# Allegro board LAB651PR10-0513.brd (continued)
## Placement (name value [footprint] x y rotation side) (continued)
RH72  10K_0402_5%  [R_0402]  160.79 13.39 180 top
RH73  100K_0402_5%  [R_0402]  144.81 21.19 180 top
RH74  0_0402_5%  [R_0402]  163.23 5.27 270 bottom
RH75  10K_0402_5%  [R_0402]  160.2 11.31 270 top
RH76  0_0402_5%  [R_0402]  161.77 5.27 270 bottom
RH77  0_0402_5%  [R0402_0OHM]  161.14 4.63 0 top
RH78  2.2K_0402_5%  [R_0402]  161.77 2.52 90 bottom
RH79  2.2K_0402_5%  [R_0402]  167.06 35.95 270 bottom
RH80  2.2K_0402_5%  [R_0402]  166.05 35.95 270 bottom
RH81  10K_0402_5%  [R_0402]  164.78 2.77 90 top
RH82  10K_0402_5%  [R_0402]  160.46 30.74 270 top
RH83  10K_0402_5%  [R_0402]  138.71 15.14 0 top
RH84  8.2K_0402_5%  [R_0402]  165.03 35.95 270 bottom
RH85  10K_0402_5%  [R_0402]  159.87 4.36 90 bottom
RH86  10K_0402_5%  [R_0402]  160.76 4.36 90 bottom
RH87  8.2K_0402_5%  [R_0402]  164.01 35.95 270 bottom
RH88  10K_0402_5%  [R_0402]  139.38 12.04 90 top
RH89  10K_0402_5%  [R_0402]  141.97 15.8 0 top
RH90  2.2K_0402_5%  [R_0402]  141.69 21.07 0 bottom
RH91  10K_0402_5%  [R_0402]  133.84 26.47 0 bottom
RH92  10K_0402_5%  [R_0402]  158.93 4.7 270 bottom
RH93  10K_0402_5%  [R_0402]  160.76 3.43 270 bottom
RH94  10K_0402_5%  [R_0402]  140.26 24.01 180 bottom
RH95  10K_0402_5%  [R_0402]  162.98 36.2 270 top
RH96  0_0603_5%  [R0603_0OHM]  149.9 28.82 0 top
RH97  0_0402_5%  [R_0402]  158.73 9.45 0 top
RH98  0_0805_5%  [R0805_0OHM]  173.16 17.11 90 top
RH99  0_0402_5%  [R_0402]  158.1 1.73 0 top
RH100  0_0603_5%  [R0603_0OHM]  169.9 10.21 0 top
RH103  0_0805_5%  [R0805_0OHM]  171.34 25.29 0 top
RH106  0_0805_5%  [R0805_0OHM]  171.16 21.01 0 top
RH107  0_0402_5%  [R0402_0OHM]  152.45 21.64 180 top
RH108  0_0402_5%  [R0402_0OHM]  150.15 24.2 270 top
RH109  0_0603_5%  [R0603_0OHM]  168.2 3.67 270 top
RH110  0_0402_5%  [R0402_0OHM]  147.49 13.46 180 top
RH111  0_0603_5%  [R0603_0OHM]  154.82 13.35 90 top
RH112  0_0402_5%  [R0402_0OHM]  146.42 26.93 90 top
RH113  0_0603_5%  [R0603_0OHM]  154.43 12.25 0 top
RH114  10K_0402_5%  [R_0402]  146.09 35.88 270 bottom
RH115  10K_0402_5%  [R_0402]  147.04 35.88 270 bottom
RH116  10K_0402_5%  [R_0402]  149.9 35.88 270 bottom
RH117  10K_0402_5%  [R_0402]  166.07 4.4 270 bottom
RH118  10K_0402_5%  [R_0402]  162.03 6.07 90 top
RH119  10K_0402_5%  [R_0402]  161.14 6.07 90 top
RH120  10K_0402_5%  [R_0402]  139.81 8.82 0 top
RH121  2.2K_0402_5%  [R_0402]  155.36 34.97 90 bottom
RH122  2.2K_0402_5%  [R_0402]  154.41 34.97 90 bottom
RH123  2.2K_0402_5%  [R_0402]  153.45 34.97 90 bottom
RH124  2.2K_0402_5%  [R_0402]  151.55 34.97 90 bottom
RH125  2.2K_0402_5%  [R_0402]  152.5 34.97 90 bottom
RH126  10K_0402_5%  [R_0402]  145.14 34.97 90 bottom
RH127  10K_0402_5%  [R_0402]  147.99 34.97 90 bottom
RH128  10K_0402_5%  [R_0402]  148.95 34.97 90 bottom
RH129  10K_0402_5%  [R_0402]  165.2 3.49 270 bottom
RH130  10K_0402_5%  [R_0402]  162.03 8.04 90 top
RH131  2.2K_0402_5%  [R_0402]  161.14 8.04 90 top
RH132  2.2K_0402_5%  [R_0402]  140.72 9.71 180 top
RH133  10K_0402_5%  [R_0402]  163 31.12 270 top
RH134  10K_0402_5%  [R_0402]  138.66 18.6 0 top
RH135  10K_0402_5%  [R_0402]  169.09 35.95 270 bottom
RL1  0_0603_5%  [MURAT_BLM18AG601SN1D_L0603_2P]  165.95 107.37 0 bottom
RL2  0_0805_5%  [R_0805]  162.15 113.21 0 bottom
RL3  0_0805_5%  [R_0805]  168.5 113.21 0 bottom
RL6  0_0603_5%  [R0603_0OHM]  170.36 100.83 90 top
RL19  75_0603_5%  [R_0603]  189.6 104.32 180 top
RL20  75_0603_5%  [R_0603]  189.6 108.39 180 top
RL21  0_0402_5%  [R_0402]  173.46 108.64 0 bottom
RL27  100K_0402_5%  [R_0402]  160.71 115.19 270 bottom
RL31  2.49K_0402_1%  [R_0402]  175.7 108.59 270 bottom
RL33  1K_0402_5%  [R_0402]  168 102.8 0 bottom
RL34  10K_0402_5%  [R_0402]  168 105.59 0 top
RL35  15K_0402_5%  [R_0402]  168 103.69 0 bottom
RL37  10K_0402_5%  [R_0402]  177.27 101.15 0 bottom
RL38  10K_0402_5%  [R_0402]  159.75 113.21 0 bottom
RL39  10K_0402_5%  [R_0402]  170.36 108.34 270 bottom
RL40  10K_0402_5%  [R_0402]  169.81 118.29 180 bottom
RM5  0_0402_5%  [R_0402]  185.1 65.66 270 top
RM6  0_0402_5%  [R0402_0OHM]  186.11 65.66 270 top
RM7  0_1206_5%  [R1206_0OHM]  173.67 59.81 90 top
RM8  10K_0402_5%  [R_0402]  187.13 65.66 270 top
RM11  100K_0402_5%  [R_0402]  181.79 64.75 90 top
RP1  1K_0804_8P4R_5%  [RP_0804_8P4R]  99.94 91.1 0 top
RP2  1K_0804_8P4R_5%  [RP_0804_8P4R]  167.38 96.71 180 top
RP15  100K_0804_8P4R_5%  [RP_0804_8P4R]  108.32 97.45 0 top
RP16  4.7K_0804_8P4R_5%  [RP_0804_8P4R]  99.94 100.5 0 top
RP34  10K_8P4R_5%  [RP_0804_8P4R]  59.38 102.36 270 bottom
RP60  2.2K_0804_8P4R_5%  [RP_0804_8P4R]  195.83 77.13 180 bottom
RPC1  1K_0804_8P4R_5%  [RP_0804_8P4R]  109.47 99.25 180 top
RPE1  2.2K_0804_8P4R_5%  [RP_0804_8P4R]  113.23 29.58 90 top
RPH1  10K_0804_8P4R_5%  [RP_0804_8P4R]  142.71 19.8 180 bottom
RPH2  10K_0804_8P4R_5%  [RP_0804_8P4R]  142.71 16.92 180 bottom
RPH3  10K_0804_8P4R_5%  [RP_0804_8P4R]  142.71 14.09 180 bottom
RPH4  10K_0804_8P4R_5%  [RP_0804_8P4R]  141.21 12.49 0 top
RPH5  2.2K_0804_8P4R_5%  [RP_0804_8P4R]  141.56 19.8 0 top
RPH6  10K_0804_8P4R_5%  [RP_0804_8P4R]  136.51 22.8 0 bottom
RPH7  10K_0804_8P4R_5%  [RP_0804_8P4R]  141.57 22.83 0 bottom
RPH10  33_0804_8P4R_5%  [RP_0804_8P4R]  136.9 26.23 0 bottom
RS8  0_0402_5%  [R_0402]  176.26 8.69 0 bottom
RS9  0_0402_5%  [R_0402]  176.26 7.8 0 bottom
RS18  0_0402_5%  [R_0402]  179.76 12.32 270 top
RS19  0_0402_5%  [R_0402]  180.52 21.72 270 top
RS20  0_0402_5%  [R_0402]  181.79 11.41 90 top
RS21  0_0402_5%  [R_0402]  178.75 20.81 90 top
RS22  0_0402_5%  [R_0402]  180.78 11.41 90 top
RS23  0_0402_5%  [R_0402]  183.83 12.32 270 top
RS24  2K_0402_5%  [R_0402]  177.86 20.81 90 top
RS25  0_0402_5%  [R_0402]  176.89 19.49 0 top
RS26  0_0402_5%  [R_0402]  185.86 11.41 90 top
RS27  4.7K_0402_5%  [R_0402]  176.97 21.72 270 top
RS28  4.7K_0402_5%  [R_0402]  179.63 21.72 270 top
RS29  0_0402_5%  [R_0402]  178.75 11.41 90 top
RS30  0_0402_5%  [R_0402]  182.81 11.41 90 top
RS31  5.1K_0402_1%  [R_0402]  184.84 12.32 270 top
RS33  4.7K_0402_5%  [R_0402]  182.56 21.72 270 top
RS34  4.7K_0402_5%  [R_0402]  177.73 12.32 270 top
RS35  4.7K_0402_5%  [R_0402]  181.54 20.81 90 top
RS36  4.7K_0402_5%  [R_0402]  176.71 12.32 270 top
RS37  0_0402_5%  [R_0402]  177.17 15.68 180 top
RS38  0_0402_5%  [R_0402]  177.17 16.57 180 top
RS41  0_0402_5%  [R_0402]  186.06 15.17 180 bottom
RS42  0_0402_5%  [R_0402]  186.06 17.2 180 bottom
RS43  0_0402_5%  [R_0402]  186.06 14.15 180 bottom
RS44  0_0402_5%  [R_0402]  186.06 16.18 180 bottom
RV1  1.69K_0402_1%  [R_0402]  66.71 78.01 270 top
RV2  1K_0402_1%  [R_0402]  61.91 98.3 270 top
RV3  1K_0402_1%  [R_0402]  68.08 78.11 270 top
RV4  100K_0402_5%  [R_0402]  75.88 76.43 90 top
RV5  45.3K_0402_1%  [R_0402]  70.24 98.48 180 bottom
RV6  45.3K_0402_1%  [R_0402]  67.37 98.48 0 bottom
RV8  8.45K_0402_1%  [R_0402]  79.76 83.49 180 top
RV9  2K_0402_1%  [R_0402]  76.56 84.76 0 top
RV11  8.45K_0402_1%  [R_0402]  79.76 81.21 180 top
RV12  4.75K_0402_1%  [R_0402]  76.56 81.21 0 top
RV13  4.75K_0402_1%  [R_0402]  76.56 87.05 0 top
RV15  8.45K_0402_1%  [R_0402]  79.76 79.05 180 top
RV16  4.75K_0402_1%  [R_0402]  76.56 79.05 0 top
RV17  1K_0402_1%  [R_0402]  59.87 101.73 270 top
RV20  1M_0402_5%  [R_0402]  79.05 76.03 270 bottom
RV21  10K_0402_5%  [R_0402]  64.45 101.73 270 bottom
RV27  0_0603_5%  [R0603_0OHM]  76.07 88.19 180 top
RV28  8.45K_0402_1%  [R_0402]  79.89 85.78 180 top
RV29  10K_0402_5%  [R_0402]  71.25 78.41 180 top
RV30  0_0603_5%  [R0603_0OHM]  71.18 76.06 90 top
RV31  0_0805_5%  [R0805_0OHM]  62.03 71.47 90 top
RV32  40.2_0402_1%  [R_0402]  55.43 70.46 90 top
RV33  40.2_0402_1%  [R_0402]  55.43 69.09 270 top
RV34  100_0402_1%  [R_0402]  57.33 68.18 90 top
RV35  100_0402_1%  [R_0402]  56.32 71.38 270 top
RV36  49.9_0402_1%  [R_0402]  65.13 96.96 0 top
RV37  10_0402_1%  [R_0402]  65.13 95.94 0 top
RV38  5.1K_0402_1%  [R_0402]  65.13 94.92 0 top
RV39  120_0402_1%  [R_0402]  60 73.26 90 top
RV40  51.1_0402_1%  [R_0402]  63.73 98.3 270 top
RV41  51.1_0402_1%  [R_0402]  62.79 98.3 270 top
RV42  4.99K_0402_1%  [R_0402]  36.63 68.05 90 bottom
RV43  4.99K_0402_1%  [R_0402]  37.52 82.68 270 bottom
RV44  4.99K_0402_1%  [R_0402]  35.74 68.97 270 bottom
RV45  4.99K_0402_1%  [R_0402]  39.55 81.77 90 bottom
RV46  243_0402_1%  [R_0402]  36.63 81.77 90 bottom
RV47  243_0402_1%  [R_0402]  33.97 68.97 270 bottom
RV48  40.2_0402_1%  [R_0402]  38.41 68.97 270 bottom
RV49  40.2_0402_1%  [R_0402]  37.52 68.97 270 bottom
RV50  4.99K_0402_1%  [R_0402]  37.39 87.86 90 bottom
RV51  4.99K_0402_1%  [R_0402]  34.47 102.37 270 top
RV52  4.99K_0402_1%  [R_0402]  38.28 88.78 270 bottom
RV53  4.99K_0402_1%  [R_0402]  35.36 101.45 90 top
RV54  40.2_0402_1%  [R_0402]  39.05 101.32 90 bottom
RV55  40.2_0402_1%  [R_0402]  38.16 101.32 90 bottom
RV56  243_0402_1%  [R_0402]  35.36 101.32 90 bottom
RV57  243_0402_1%  [R_0402]  27.41 91.62 0 top
RV58  4.7K_0402_5%  [R_0402]  52.94 105.8 0 bottom
RV59  10K_0402_5%  [R_0402]  69.42 77.19 90 top
RV60  0_0603_5%  [R0603_0OHM]  71.28 88.7 270 top
RV71  10K_0402_5%  [R_0402]  83.75 89.29 270 bottom
RV72  10K_0402_5%  [R_0402]  84.89 95.74 90 bottom
RV73  10K_0402_5%  [R_0402]  82.73 88.37 90 bottom
RV74  10K_0402_5%  [R_0402]  83.88 96.65 270 bottom
RV75  33_0402_5%  [R_0402]  82.86 96.65 270 bottom
RV76  33_0402_5%  [R_0402]  85.91 96.65 270 bottom
RV77  33_0402_5%  [R_0402]  79.23 90.35 0 bottom
RV78  33_0402_5%  [R_0402]  79.23 93.91 0 bottom
RV79  10K_0402_5%  [R_0402]  84.77 89.29 270 bottom
RV81  4.7K_0402_5%  [R_0402]  66.22 100.82 90 bottom
RV82  4.7K_0402_5%  [R_0402]  65.33 100.82 90 bottom
RV83  16.2K_0402_1%  [R_0402]  73.21 99.42 90 bottom
RV84  10K_0402_5%  [R_0402]  80.14 94.8 180 bottom
RV87  10K_0402_5%  [R_0402]  80.14 92.13 180 bottom
RV88  10K_0402_5%  [R_0402]  79.23 91.24 0 bottom
RV89  10K_0402_5%  [R_0402]  79.23 95.69 0 bottom
RV90  0_0402_5%  [R_0402]  61.91 100.82 90 top
RV91  10K_0402_5%  [R_0402]  62.92 101.73 270 top
RV92  0_0402_5%  [R_0402]  72.32 91.29 90 top
RV93  0_0603_5%  [R_0603]  77.34 94.34 180 top
RV94  0_0603_5%  [R_0603]  77.34 93.11 180 top
RV146  4.7K_0402_5%  [R_0402]  45.07 107.47 90 bottom
RV147  4.7K_0402_5%  [R_0402]  77.4 96.24 90 top
RV148  10K_0402_5%  [R_0402]  72.24 96.19 0 top
RV149  0_0402_5%  [R_0402]  72.24 97.08 0 top
RV151  10K_0402_5%  [R_0402]  62.85 101.73 270 bottom
RV152  10K_0402_5%  [R_0402]  61.96 100.82 90 bottom
RV153  0_0402_5%  [R_0402]  64.63 91.78 270 top
RV154  5.1K_0402_1%  [R_0402]  58.86 101.73 270 top
RV155  0_0402_5%  [R_0402]  79.23 88.57 0 bottom
RV156  0_0402_5%  [R_0402]  79.23 89.46 0 bottom
RV157  0_0402_5%  [R_0402]  79.23 93.02 0 bottom
RV158  0_0402_5%  [R0402_0OHM]  70.01 79.43 0 top
RV159  0_0402_5%  [R0402_0OHM]  69.83 80.7 0 top
RV160  10_0402_5%  [R_0402]  71.74 79.43 0 top
RV161  10_0402_5%  [R_0402]  71.74 80.7 0 top
RV162  4.7K_0402_5%  [R_0402]  79.89 77.91 180 bottom
RV163  4.7K_0402_5%  [R_0402]  78.97 76.89 0 bottom
RV164  0_0402_5%  [R_0402]  49.51 111.94 0 bottom
RV165  0_0402_5%  [R_0402]  49.51 111.05 0 bottom
RX2  100K_0402_5%  [R_0402]  9.33 76.59 270 top
RX3  100K_0402_5%  [R_0402]  9.38 74.6 0 top
RX4  100K_0402_5%  [R_0402]  13.58 72.94 270 top
RX5  0_0805_5%  [R_0805]  4.59 78.92 180 top
RX7  0_0402_1%  [R_0402]  10.85 84.81 90 top
RX8  0_0402_5%  [R_0402]  9.84 84.81 90 top
RX9  10K_0402_5%  [R_0402]  4.3 80.45 0 top
RX10  10K_0402_5%  [R_0402]  24.44 75.06 270 top
RX12  10K_0402_5%  [R_0402]  197.34 73.97 0 top
RX13  100K_0402_5%  [R_0402]  189.97 93.15 0 top
RX14  100K_0402_5%  [R_0402]  192.67 76 180 top
RX15  150K_0402_5%  [R_0402]  197.34 71.3 0 top
RX21  0_0402_5%  [R_0402]  5.25 85.35 180 top
RX22  0_0402_5%  [R_0402]  5.25 86.36 180 top
RX23  0_0402_5%  [R0402_0OHM]  11.31 89.08 180 top
RX24  100K_0402_5%  [R_0402]  5.21 90.1 180 top
RX25  0_0402_5%  [R0402_0OHM]  5.21 87.56 180 top
RX26  100K_0402_5%  [R_0402]  4.3 81.46 0 top
RX27  0_0603_1%  [R0603_0OHM]  5.43 83.43 180 top
RX28  0_0603_5%  [R0603_0OHM]  14.09 97.21 180 top
RX29  0_0603_5%  [R_0603]  14.15 99.94 270 top
RX30  0_0603_5%  [R_0603]  12.88 99.94 270 top
RX34  20K_0402_5%  [R_0402]  198.25 72.19 180 top
RX35  100K_0402_5%  [R_0402]  5.21 89.08 180 top
RX36  0_0402_5%  [R_0402]  10.39 88.07 0 top
RX37  0_0402_5%  [R_0402]  14.61 103.81 180 top
RX38  0_0402_5%  [R_0402]  10.14 102.54 0 top
RX39  10K_0402_5%  [R_0402]  12.63 104.78 270 top
RX40  10K_0402_5%  [R_0402]  13.7 104.83 0 top
RX179  665_0402_1%  [R_0402]  195.21 82.22 180 top
RX180  665_0402_1%  [R_0402]  195.21 83.24 180 top
RX181  665_0402_1%  [R_0402]  195.21 78.67 180 top
RX182  665_0402_1%  [R_0402]  195.21 79.68 180 top
RX183  665_0402_1%  [R_0402]  195.21 85.78 180 top
RX184  665_0402_1%  [R_0402]  195.21 86.8 180 top
RX185  665_0402_1%  [R_0402]  195.21 89.34 180 top
RX186  665_0402_1%  [R_0402]  195.21 90.35 180 top
RZ10  100K_0402_5%  [R_0402]  120.83 24.01 270 top
RZ19  100K_0402_5%  [R_0402]  123.37 20.71 270 top
RZ21  100K_0402_5%  [R_0402]  122.66 25.07 0 top
RZ24  470_0402_5%  [R_0402]  160.71 38.99 270 top
RZ25  0_0402_5%  [R0402_0OHM]  72.5 29.84 0 top
RZ27  470_0402_5%  [R_0402]  135.31 37.22 270 top
RZ591  10K_0402_5%  [R_0402]  122.36 20.71 270 top
SW1  SMT1-05-A_4P  [SW_SMT1-05-A_4P]  172.28 113.17 90 top
T3  -  [TPC12]  120.54 101.82 180 bottom
T4  -  [TPC12]  119.08 102.58 180 bottom
T5  -  [TPC12]  120.59 103.17 180 bottom
T10  -  [TPC12]  134.21 88.42 0 top
T11  -  [TPC12]  135.13 89.34 0 top
T12  -  [TPC12]  120.11 95.1 180 bottom
T13  -  [TPC12]  129.61 88.22 0 top
T86  PAD  [TPC12]  58.18 99.41 0 top
T94  PAD  [TPC12]  169.42 106.63 180 bottom
T95  PAD  [TPC12]  172.19 106.76 180 bottom
T97  -  [TPC12]  144.49 25.57 180 bottom
T98  -  [TPC12]  148.83 5.36 180 bottom
T99  -  [TPC12]  157.28 34.09 180 bottom
T101  -  [TPC12]  160.97 14.28 0 top
T102  -  [TPC12]  158.9 5.59 180 bottom
T103  -  [TPC12]  110.97 13.48 0 bottom
T104  -  [TPC12]  112.53 28.19 0 top
T106  -  [TPC12]  124.67 24.58 0 bottom
T107  -  [TPC12]  156.65 35.62 180 bottom
T108  -  [TPC12]  158.3 35.62 180 bottom
T110  -  [TPC12]  124.87 21.66 180 bottom
T111  -  [TPC12]  105.15 16.32 270 bottom
T112  -  [TPC12]  105.67 17.49 270 bottom
T118  -  [TPC12]  144.34 12.76 0 top
T120  -  [TPC12]  119.73 32.36 180 bottom
T126  -  [TPC12]  164.65 97.69 0 top
T127  -  [TPC12]  140.02 17.88 180 bottom
T128  -  [TPC12]  124.64 33.58 180 bottom
T129  -  [TPC12]  145.64 12.81 0 top
T130  -  [TPC12]  81.59 98.61 0 top
T131  -  [TPC12]  85.15 96.45 0 top
T132  -  [TPC12]  83.37 98.1 0 top
T201  -  [TPC12]  61.08 90.53 0 top
T202  -  [TPC12]  59.71 89.86 0 top
T203  -  [TPC12]  72.28 90.35 0 top
T204  -  [TPC12]  67.94 89.97 0 top
T205  -  [TPC12]  70.8 92.64 0 top
T206  -  [TPC12]  71.02 89.87 0 top
T207  -  [TPC12]  69.16 90.44 0 top
T208  -  [TPC12]  70.19 94.24 0 top
T209  -  [TPC12]  70.03 91.37 0 top
T210  -  [TPC12]  69.27 93.02 0 top
T211  -  [TPC12]  68.23 91.7 0 top
T212  -  [TPC12]  66.99 91.11 0 top
T213  -  [TPC12]  67.49 92.79 0 top
T214  -  [TPC12]  68.26 93.91 0 top
T215  -  [TPC12]  69.14 95.05 0 top
T216  -  [TPC12]  65.72 90.73 0 top
T217  -  [TPC12]  66.07 92.08 0 top
T218  -  [TPC12]  69.64 85.44 0 top
T221  -  [TPC12]  67.62 95.31 0 top
T222  -  [TPC12]  68.85 96.71 0 top
T223  -  [TPC12]  62.24 98.23 180 bottom
T224  -  [TPC12]  62.83 96.88 180 bottom
T3861  PAD  [TPC12]  174.16 65.61 0 top
T3862  PAD  [TPC12]  176.21 65.46 0 top
T4927  PAD  [TPC12]  182.54 66.7 0 top
T4928  PAD  [TPC12]  183.32 64.89 0 top
T4929  PAD  [TPC12]  183.86 66.07 0 top
T4930  -  [TPC12]  76.64 89.97 180 bottom
TL2  350UH_LF-H1201P-2  [LANKO_LF-H1201P-2_16P]  180.21 101.91 90 bottom
U1  S IC SN74AVC2T45DCTR_SM8  [SN74LVC2T45DCTR_SM8]  81.63 94.31 0 bottom
U2  21807-A13-HUDSON-M3_FCBGA656  [21807-A11-HUDSON-M3_FCBGA_656P]  146.35 8.57 0 bottom
U6  APE8990GN3B DFN 14P DUAL LOAD SW  [TPS22966DPUR_SON14_2X3]  72.14 31.67 0 top
U15  APE8990GN3B DFN 14P DUAL LOAD SW  [TPS22966DPUR_SON14_2X3]  129.24 3.17 0 top
U16  APE8990GN3B DFN 14P DUAL LOAD SW  [TPS22966DPUR_SON14_2X3]  96.36 63.68 90 top
U64  -  [74AUP1G07GW_TSSOP5]  106.37 94.89 90 top
U67  -  [74AUP1G07GW_TSSOP5]  106.37 97.56 90 top
U68  -  [74AUP1G07GW_TSSOP5]  106.37 92.23 90 top
U2407  F75303M_MSOP10  [EMC1403-2-AIZL-TR_MSOP10]  125.29 35.22 270 top
UA1  -  [ALC3234-CG_MQFN48_6X6]  198.73 16.44 180 bottom
UC1  KAVERI-FP3-2.7G_BGA854  [KAVERI-FP3-2P7G_BGA_854P]  123.1 108.7 270 bottom
UE1  KB9012QF-A4_LQFP128_14X14  [KB9012QF-A2_LQFP128_14X14]  121.19 14.96 180 bottom
UE3  APE8875M SOP 8P  [G993P1UF_SOP8]  6.79 69.57 180 top
UE4  TPS22967DSGR_SON8_2X2  [AOZ1336_DFN8_2X2]  9.5 65.19 270 top
UG1  SLG3NB302VTR _TQFN16_2X3  [SLG3NB274VTR_TQFN16_2X3]  135.13 13.65 0 bottom
UH1  MC74VHC1G08DFT2G SC70 5P  [NC7SZ08P5X_NL_SC70-5]  141.15 32.57 180 bottom
UI5  -  [SY6288D20AAC_SOT23-5]  193.92 47.75 90 top
UI6  -  [SY6288D20AAC_SOT23-5]  193.92 43.43 90 top
UI7  -  [SY6288D20AAC_SOT23-5]  17.12 51.9 180 top
UL1  RTL8106E-CG_QFN32_4X4  [RTL8106EUS-CG_QFN32_4X4]  175.46 104.96 270 bottom
UL2  -  [APL3512ABI-TRG_SOT23-5]  163.95 114.91 180 bottom
UL3  -  [SY6288C20AAC_SOT23-5]  170.04 114.81 180 bottom
US2  -  [PS8520BTQFN20GTR2_TQFN20_4X4]  183.06 15.44 90 top
USPI1  EN25QH64-104HIP_SO8  [W25Q64FVSSIG_SO8]  183.95 18.91 180 bottom
UV1  2160856030-A0_FCBGA631  [216-0842024-A11-MAR_FCBGA_631P]  53.2 94.5 270 bottom
UV2  -  [MC74VHC1G08DFT2G_SC70-5]  78.18 77.84 180 top
UV3  -  [ADM1032ARMZ_MSOP8]  51.36 109.72 270 bottom
UV4  MC74VHC1G08DFT2G_SC70-5  [MC74VHC1G09DFT2G_SC70-5]  74.7 93.24 180 top
UV5  H5TC2G63FFR-11C FBGA 96P  [K4W1G1646E-HC12_FBGA_96P-A39]  42.95 72.12 90 bottom
UV6  H5TC2G63FFR-11C FBGA 96P  [K4W1G1646E-HC12_FBGA_96P-A39]  42.95 78.52 270 top
UV7  H5TC2G63FFR-11C FBGA 96P  [K4W1G1646E-HC12_FBGA_96P-A39]  42.95 98.33 270 top
UV8  H5TC2G63FFR-11C FBGA 96P  [K4W1G1646E-HC12_FBGA_96P-A39]  42.95 91.93 90 bottom
UX4  -  [SY6288C20AAC_SOT23-5]  21.2 74.17 0 top
X1  25MHZ_10PF_7V25000014  [Y_FSX3M-25PM20FDO_4P]  170.38 4.18 0 bottom
Y1  25MHZ_10PF_7V25000014  [Y_FSX3M-25PM20FDO_4P]  134.13 18.43 180 bottom
Y2  S CRYSTAL 32.768KHZ 12.5PF CM7V-12520  [Y_9H03200019_2P]  142.53 6.94 90 bottom
YL2  25MHZ_10PF_7V25000014  [Y_FSX3M-25PM20FDO_4P]  174.51 109.87 180 bottom
YV1  27MHZ_10PF_7V27000050  [Y_7V27000011_4P]  83.8 76.04 270 bottom

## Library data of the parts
C5 C58-C60 C68-C71 C77-C81 C88-C90 CE16 CI6 CI12 CI18 CI44 CS7 CX3 CX7 CX8 CX49 CZ3 CZ13 PC112 PC115 PC205 PC206 PC211 PC212 PC303 PC304 PC503-PC505 PC519-PC521 PC702 PC703 PC717-PC720 PC1023 PC1024 PC1041 PC1046 PC1048 PC1049 PC1052 PC1102 = C_0805
C6-C9 C11 C12 C14 C15 C17-C20 C29 C30 C53-C55 C57 C61-C66 C72 C73 C75 C76 C93-C96 C99 C100 C103-C114 C119 C120 C123 C124 C126 C127 C129 C151-C166 C343 C344 C348 C349 C935 C936 C983 C986 C987 C1014 C2498 C2500 C2502 C2504 C2505 C4311-C4314 C4321 C4322 CA21 CA22 CA24 CA25 CA29-CA33 CA38-CA40 CA51 CA54 CA56 CA58 CA60 CA65 CA69 CC84-CC91 CE1-CE11 CE14 CE15 CE17 CE18 CE20 CE23 CE24 CE26 CE27 CE29 CE58-CE61 CH1-CH17 CH20 CH23 CH25-CH27 CH29 CH31-CH34 CH36 CH37 CH39-CH41 CH44 CH45 CH50-CH52 CH56-CH58 CH61-CH73 CH75-CH86 CH88-CH90 CH92 CH466 CI2-CI5 CI7 CI9-CI11 CI13-CI17 CI26 CI45-CI47 CL3 CL5-CL10 CL12 CL15 CL16 CL19 CL30 CL31 CL36 CL37 CL39 CL41 CM5 CM7 CM9 CM10 CS5 CS6 CS27 CS30-CS42 CV1-CV18 CV20-CV22 CV26 CV28-CV35 CV39-CV42 CV46-CV53 CV56-CV60 CV62-CV66 CV71-CV80 CV82 CV85-CV87 CV89 CV90 CV92-CV102 CV104-CV117 CV119-CV135 CV137-CV150 CV152-CV168 CV170-CV191 CV357-CV364 CVT90 CX1 CX2 CX4 CX11 CX20 CX21 CX23-CX31 CX50 CZ5 CZ9 CZ15 PC1-PC5 PC7-PC9 PC13 PC16 PC102 PC103 PC108 PC111 PC113 PC114 PC118 PC119 PC201-PC203 PC207 PC208 PC210 PC214 PC215 PC301 PC302 PC306 PC309 PC311 PC314-PC316 PC402 PC404 PC408-PC410 PC412 PC415 PC416 PC500 PC501 PC506 PC508-PC510 PC512 PC513 PC522 PC523 PC525-PC527 PC529-PC535 PC701 PC704 PC708 PC712 PC715 PC716 PC721 PC723 PC725 PC727 PC840-PC852 PC859 PC860 PC869 PC871 PC872 PC914-PC921 PC943-PC949 PC1019 PC1022 PC1025 PC1027 PC1028 PC1030 PC1031 PC1033 PC1034 PC1036 PC1040 PC1042 PC1045 PC1047 PC1050 PC1051 PC1100 PC1101 PC1104 PC1106 PC1109 PC1302 PC1304 PC1306 PC1307 = C_0402
C10 C74 C82-C85 C115-C118 C121 C122 C125 C128 CA1 CA2 CA23 CA53 CA55 CA57 CA59 CA61-CA64 CA67 CA68 CA71 CA74 CE22 CE25 CE56 CE57 CH30 CH35 CH42 CH43 CH46 CH53 CH59 CH60 CH74 CH87 CH91 CI40 CI43 CL4 CL13 CL14 CL17 CL38 CM4 CM6 CV19 CV27 CV38 CV43-CV45 CV54 CV55 CV61 CV67-CV70 CV81 CV83 CV84 CV88 CV91 CV103 CV118 CV136 CV151 CV169 CX5 CX22 CZ1 CZ2 CZ4 CZ14 PC100 PC104-PC106 PC109 PC110 PC200 PC204 PC209 PC305 PC307 PC310 PC312 PC313 PC400 PC401 PC403 PC405-PC407 PC411 PC413 PC414 PC502 PC507 PC511 PC514 PC515 PC524 PC528 PC700 PC705-PC707 PC709-PC711 PC713 PC714 PC722 PC726 PC728 PC853-PC858 PC901-PC913 PC931-PC942 PC1020 PC1021 PC1026 PC1029 PC1032 PC1035 PC1043 PC1044 PC1103 PC1105 PC1300 PC1301 PC1303 PC1305 PC1308 PC1309 = C_0603
CI1 CI8 PC101 PC107 = C_MP6VLPS220MC4R2
CL33 = C_1206
CLRP1 = SHORTPADS: User Part Number: PART#
CX12-CX19 PR100 PR101 PR201 PR202 PR209 PR303 PR311 PR404 PR408 PR528 PR529 PR539 PR547 PR717 PR719 PR1022 PR1027 PR1049 PR1050 PR1060-PR1064 PR1103 PR1300 R24 R445 R446 R623 RA4 RE4 RE15 RE26-RE29 RE31 RE33 RE37 RE44 RE61 RE80 RE336 RE337 RH10-RH13 RH15 RH16 RH18 RH27 RH52 RH66 RH77 RH107 RH108 RH110 RH112 RM6 RV158 RV159 RX23 RX25 RZ25 = R0402_0OHM
D6 D7 DH1 DH2 = RB751V40_SC76-2
D29 D30 = DB2J31400L_SOD323-2
DA8 = BAT54C-7-F_SOT23-3
DA10 DA12-DA14 = AZ5125-02SPR7G_SOT23-3
DE2 = L03ESDL5V0CC3-2_SOT23-3
DI1 DI4 = IP4292CZ10-TBR_XSON10_2P5X1
DI2 DI5 = L30ESDL5V0C3-2_SOT23-3
DX1 = RB751V-40_SOD323-2
DX2 = PESD5V0U2BT_SOT23-3
FD1-FD4 = FIDUCIAL_C40M80
FE1 = F_1812L075-24DR
FX1 = F_1206L150PR
H1 H20 H21 = H_2P8N
H2-H9 H11 H12 = H_2P8
H13-H16 = H_3P6
H17-H19 = H_3P3
H22 = H_2P8X3P3N
H23 = H_2P8X4P8N
HE1 LA3-LA6 LV2-LV4 LV7 LV8 LV25 LV26 PH1 PH500 PH501 PH1002 PH1003 PR1 PR3 PR4 PR6-PR11 PR15 PR16 PR18 PR20 PR23-PR26 PR28 PR29 PR31 PR33 PR102 PR104-PR110 PR114 PR115 PR204 PR205 PR207 PR208 PR301 PR304 PR306 PR307 PR309 PR312 PR313 PR401 PR403 PR405 PR407 PR409 PR410 PR500 PR502 PR508 PR511 PR513-PR515 PR518 PR519 PR526 PR527 PR530 PR535-PR538 PR540 PR541 PR545 PR549 PR550 PR552-PR555 PR557-PR561 PR565 PR567 PR569 PR571 PR573 PR701-PR706 PR708 PR710-PR712 PR714-PR716 PR718 PR722-PR729 PR1020 PR1025 PR1029-PR1033 PR1035 PR1037 PR1038 PR1040-PR1046 PR1048 PR1052 PR1053 PR1056 PR1058 PR1059 PR1102 PR1105 PR1107 PR1108 PR1110 PR1301 PR1302 PR1304 R1 R3 R5 R6 R8 R13-R18 R22 R23 R25-R40 R47 R48 R50 R54-R59 R65 R120-R122 R365 R384 R407 R435-R438 R537 R538 R616 R617 R620-R622 R782 R783 R785 R787 R790 R791 R793 R796 R2448 R2450 RA1-RA3 RA5-RA12 RA19 RA28 RA34 RA53 RA55 RA56 RA79-RA84 RA130 RA155 RA165 RA166 RA1109 RA1112 RA1113 RC8 RC9 RC13 RC78 RE3 RE5-RE13 RE16 RE21 RE30 RE32 RE34 RE38-RE40 RE43 RE45-RE47 RE49 RE50 RE58 RE60 RE62 RE63 RE68-RE71 RE329 RE332 RE333 RE504 RH1-RH7 RH14 RH17 RH19-RH26 RH28 RH29 RH34 RH35 RH37-RH41 RH51 RH53 RH54 RH56-RH61 RH64 RH65 RH67-RH70 RH72-RH76 RH78-RH95 RH97 RH99 RH114-RH135 RL21 RL27 RL31 RL33-RL35 RL37-RL40 RM5 RM8 RM11 RS8 RS9 RS18-RS31 RS33-RS38 RS41-RS44 RV1-RV6 RV8 RV9 RV11-RV13 RV15-RV17 RV20 RV21 RV28 RV29 RV32-RV59 RV71-RV79 RV81-RV84 RV87-RV92 RV146-RV149 RV151-RV157 RV160-RV165 RX2-RX4 RX7-RX10 RX12-RX15 RX21 RX22 RX24 RX26 RX34-RX40 RX179-RX186 RZ10 RZ19 RZ21 RZ24 RZ27 RZ591 = R_0402
J11 J13-J16 PJP100-PJP103 PJP200 PJP201 PJP300 PJP401 PJP1100 PJP1101 = JUMP_43X118
J519 JP3 PJP203 = JUMP_43X39
JDIMM1 = BELLW_80001-1021_204P
JEDP = STARC_107K40-000001-G2_40P
JFAN = ACES_88231-03041_3P
JHDD = E-T_4260K-F10N-00L_10P
JHDMI = CONCR_099ATAC19NBLCNF_19P
JHDT1 = SAMTE_ASP-136446-07-B_20P-T
JHP = SINGA_2SJ3080-001111F_6P
JIO = ACES_51524-0160N-001_16P
JKB = HB_A823020-SBHR21_30P
JKBBL = ACES_50524-00401-P01_4P-T
JLAN = J-L_TNBNRAC80015008_8P
JLED JTP = ACES_51524-0080N-001_8P
JNGFF = LOTES_APCI0019-P009A_67P
JP13 PJP301 PJP302 PJP400 PJP402 PJP403 PJP1300 PJP1301 = JUMP_43X79
JRTC = ACES_50271-0020N-001_2P
JSPK = ACES_50278-00401-001_4P
JUSB1 JUSB2 = TAITW_PUBAU6-09FLBS1NN4H0_9P
LA1 LV6 = MURAT_BLM15BB221SN1D_2P
LA7-LA10 = MURAT_BLM15BD601SN1D_2P
LE1 LE2 = KC_FBMA-L11-160808-800LMT_2P
LH1 LH6 LH7 LH9-LH14 = CHENG_MBK1608221YZF_2P
LH5 LH15 RE1 RE2 RE59 RL2 RL3 RX5 = R_0805
LI1 LI3 LI4 LI6 = MURAT_DLW21SN670HQ2L_4P
LI2 LI5 LI7 LI8 LX2-LX6 = KC_WCM-2012HS-900T_4P
LL1 = MURAT_LQM2MPN2R2NG0L_2P
LX1 = KC_FBMA-L11-201209-221LMA30_2P
PBATT = ALLTO_C144LS-109A9-L_9P-T
PC213 PC1108 = C_MP6VU330MC6
PC300 PC838 PC839 PC922 PC952 = C_D2
PC518 = C_ECST250ADA101MF611
PC836 PC837 PC923 PC924 PC950 PC951 = C_D3
PD1 PD2 PD101 = TVNST52302AB0_SOT523-3
PJPDC = ACES_50299-00501-003_5P
PL1 PL3-PL5 PL201 PL1000 PL1100 = TAIYO_FBMJ4516HS720NT_2P
PL2 = MURAT_BLM15AG102SN1D_2P
PL100 PL101 PL200 PL1101 = L_7X7X3_M_2P
PL102 PL300 = L_5X5X3_M_2P
PL301 = TAI-T_HCB2012KF-121T50_2P
PL302 PL401 = TOKO_1239AS-H-1R0M-P2_2P
PL400 PL1300 = CYNTE_PCMC042T-R47MN_2P
PL500 PL501 PL1002 PL1003 = PANAS_ETQP4LR15AFM_4P
PL502 = L_1812-1806
PL700 = CYNTE_PCMB104T-100MS_2P
PL701 = L_4X4X2_F_2P
PQ1 PQ2 PQ709 PQ710 PQ713 QH31 = 2N7002DW-T-R7_SOT363-6
PQ5 = RHU002N06_SOT323-3
PQ6 = FDV301N_NL_SOT23-3
PQ101-PQ104 PQ200 PQ201 PQ301 PQ303 PQ1100 PQ1101 = SIS412DN-T1-GE3_POWERPAK8-5
PQ500 PQ501 = CSD86350Q5D_SON8
PQ701 PQ1003 PQ1005 = MDU1516URH_POWERDFN56-8-5
PQ703 PQ1004 PQ1006 = SIR472DP-T1-GE3_POWERPAK8-5
PQ704 PQ706 = AO4407AL_SO8
PQ705 = SI4459ADY-T1-GE3_SO8
PQ707 = DTA144EUA_SC70-3
PQ708 PQ711 PQ712 = DTC115EUA_SC70-3
PQ714 QM1 QV7 QZ13 QZ15 = SSM3K7002FU_SC70-3
PR5 PR112 PR113 PR203 PR305 PR516 PR546 PR707 PR721 PR730 PR1036 PR1054 PR1104 PR1303 = R_1206
PR103 PR111 PR200 PR206 PR210 PR302 PR310 PR402 PR406 PR510 PR520 PR521 PR542 PR709 PR1024 PR1034 PR1039 PR1055 PR1057 PR1101 RE330 RE331 RL19 RL20 RV93 RV94 RX29 RX30 = R_0603
PR507 PR531 PR713 RA29-RA32 RA1110 RA1111 RH96 RH100 RH109 RH111 RH113 RL6 RV27 RV30 RV60 RX27 RX28 = R0603_0OHM
PR700 PR720 = R_1206_4P-D
PU100 = TPS51285BRUKR_QFN20_3X3
PU200 = RT8207MZQW_WQFN20_3X3
PU300 PU1100 = TPS51212DSCR_SON10_3X3
PU301 PU401 = SY8032ABC_SOT23-6
PU400 = SY8036LDBC_DFN10_3X3
PU500 = NCP6151S52MNR2G_QFN52_6X6
PU700 = BQ24745RHDR_QFN28_5X5
PU1000 = ISL62771HRTZ-T_TQFN40_5X5
PU1300 = SY8036DBC_DFN10_3X3
Q3 QC1 = 2N7002_SOT23-3
Q9 Q10 = BSH111_SOT23-3
Q12 = MMBT3904_SOT23-3
Q20 QE30 QX3 = 2N7002K_SOT23-3
Q52 Q78 Q2507 QA5 QA6 QH2 QV8 QX4 QX6 QX7 = DMN66D0LDW-7_SOT363-6
Q2407 Q2408 = MMST3904-7-F_SOT323-3
QE4 = 2N7002BKW_SOT323-3
QE5 = SI3456BDV-T1-E3_TSOP6
QV1 = 2N7002KDWH_SOT363-6
QX2 = SI3457CDV-T1-GE3_TSOP6
QX5 = MMBT3904_NL_SOT23-3
RH98 RH103 RH106 RV31 = R0805_0OHM
RL1 = MURAT_BLM18AG601SN1D_L0603_2P
RM7 = R1206_0OHM
RP1 RP2 RP15 RP16 RP34 RP60 RPC1 RPE1 RPH1-RPH7 RPH10 = RP_0804_8P4R
SW1 = SW_SMT1-05-A_4P
T3-T5 T10-T13 T86 T94 T95 T97-T99 T101-T104 T106-T108 T110-T112 T118 T120 T126-T132 T201-T218 T221-T224 T3861 T3862 T4927-T4930 = TPC12
TL2 = LANKO_LF-H1201P-2_16P
U1 = SN74LVC2T45DCTR_SM8
U2 = 21807-A11-HUDSON-M3_FCBGA_656P
U6 U15 U16 = TPS22966DPUR_SON14_2X3
U64 U67 U68 = 74AUP1G07GW_TSSOP5
U2407 = EMC1403-2-AIZL-TR_MSOP10
UA1 = ALC3234-CG_MQFN48_6X6
UC1 = KAVERI-FP3-2P7G_BGA_854P
UE1 = KB9012QF-A2_LQFP128_14X14
UE3 = G993P1UF_SOP8
UE4 = AOZ1336_DFN8_2X2
UG1 = SLG3NB274VTR_TQFN16_2X3
UH1 = NC7SZ08P5X_NL_SC70-5
UI5-UI7 = SY6288D20AAC_SOT23-5
UL1 = RTL8106EUS-CG_QFN32_4X4
UL2 = APL3512ABI-TRG_SOT23-5
UL3 UX4 = SY6288C20AAC_SOT23-5
US2 = PS8520BTQFN20GTR2_TQFN20_4X4
USPI1 = W25Q64FVSSIG_SO8
UV1 = 216-0842024-A11-MAR_FCBGA_631P
UV2 = MC74VHC1G08DFT2G_SC70-5
UV3 = ADM1032ARMZ_MSOP8
UV4 = MC74VHC1G09DFT2G_SC70-5
UV5-UV8 = K4W1G1646E-HC12_FBGA_96P-A39
X1 Y1 YL2 = Y_FSX3M-25PM20FDO_4P
Y2 = Y_9H03200019_2P
YV1 = Y_7V27000011_4P

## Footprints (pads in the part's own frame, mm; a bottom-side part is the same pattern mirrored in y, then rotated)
2N7002_SOT23-3
  oval 1.016x1.524 smd: 1(0,0) 2(0.965,2.083) 3(-0.965,2.083)
2N7002BKW_SOT323-3
  oval 0.61x0.559 smd: 1(0,0) 2(-0.65,-1.85) 3(0.65,-1.85)
2N7002DW-T-R7_SOT363-6
  oval 0.381x1.397 smd: 1(0,0) 2(0.65,0) 3(1.3,0) 4(1.3,1.725) 5(0.65,1.725) 6(0,1.725)
2N7002K_SOT23-3
  oval 1.016x1.524 smd: 1(0,0) 2(0.965,2.083) 3(-0.965,2.083)
2N7002KDWH_SOT363-6
  oval 0.356x0.889 smd: 1(0,0) 2(0.65,0) 3(1.3,0) 4(1.3,1.6) 5(0.65,1.6) 6(0,1.6)
74AUP1G07GW_TSSOP5
  oval 0.381x1.346 smd: 1(0,0) 2(0.65,0) 3(1.3,0) 4(1.3,1.79) 5(0,1.79)
216-0842024-A11-MAR_FCBGA_631P
  round 0.406 smd: A3(0.8,0) A30(20.8,0) A32(21.6,0) AB7(3.2,-15) AB8(4,-15) AB9(4.8,-15) AB10(5.6,-15) AB23(16,-15) AB24(16.8,-15) AB25(17.6,-15) AB26(18.4,-15) AC11(6.6,-16) AC13(7.8,-16) AC14(9,-16) AC16(10.2,-16) AC17(11.4,-16) AC19(12.6,-16) AC20(13.8,-16) AC22(15,-16) AD11(6.6,-16.8) AD13(7.8,-16.8) AD14(9,-16.8) AD16(10.2,-16.8) AD17(11.4,-16.8) AD19(12.6,-16.8) AD20(13.8,-16.8) AD22(15,-16.8) AE11(6.6,-17.6) AE13(7.8,-17.6) AE14(9,-17.6) AE16(10.2,-17.6) AE17(11.4,-17.6) AE19(12.6,-17.6) AE20(13.8,-17.6) AE22(15,-17.6) AF11(6.6,-18.4) AF13(7.8,-18.4) AF14(9,-18.4) AF16(10.2,-18.4) AF17(11.4,-18.4) AF19(12.6,-18.4) AF20(13.8,-18.4) AF22(15,-18.4) AK1(0,-20.8) AK3(0.8,-20.8) AK30(20.8,-20.8) AK32(21.6,-20.8) AM1(0,-21.6) AM3(0.8,-21.6) AM30(20.8,-21.6) AM32(21.6,-21.6) C1(0,-0.8) C3(0.8,-0.8) C30(20.8,-0.8) C32(21.6,-0.8) G11(6.6,-3.2) G13(7.8,-3.2) G14(9,-3.2) G16(10.2,-3.2) G17(11.4,-3.2) G19(12.6,-3.2) G20(13.8,-3.2) G22(15,-3.2) H11(6.6,-4) H13(7.8,-4) H14(9,-4) H16(10.2,-4) H17(11.4,-4) H19(12.6,-4) H20(13.8,-4) H22(15,-4) J11(6.6,-4.8) J13(7.8,-4.8) J14(9,-4.8) J16(10.2,-4.8) J17(11.4,-4.8) J19(12.6,-4.8) J20(13.8,-4.8) J22(15,-4.8) K11(6.6,-5.6) K13(7.8,-5.6) K14(9,-5.6) K16(10.2,-5.6) K17(11.4,-5.6) K19(12.6,-5.6) K20(13.8,-5.6) K22(15,-5.6) L7(3.2,-6.6) L8(4,-6.6) L9(4.8,-6.6) L10(5.6,-6.6) L23(16,-6.6) L24(16.8,-6.6) L25(17.6,-6.6) L26(18.4,-6.6) N7(3.2,-7.8) N8(4,-7.8) N9(4.8,-7.8) N10(5.6,-7.8) N23(16,-7.8) N24(16.8,-7.8) N25(17.6,-7.8) N26(18.4,-7.8) P7(3.2,-9) P8(4,-9) P9(4.8,-9) P10(5.6,-9) P23(16,-9) P24(16.8,-9) P25(17.6,-9) P26(18.4,-9) T7(3.2,-10.2) T8(4,-10.2) T9(4.8,-10.2) T10(5.6,-10.2) T23(16,-10.2) T24(16.8,-10.2) T25(17.6,-10.2) T26(18.4,-10.2) U7(3.2,-11.4) U8(4,-11.4) U9(4.8,-11.4) U10(5.6,-11.4) U23(16,-11.4) U24(16.8,-11.4) U25(17.6,-11.4) U26(18.4,-11.4) W7(3.2,-12.6) W8(4,-12.6) W9(4.8,-12.6) W10(5.6,-12.6) W23(16,-12.6) W24(16.8,-12.6) W25(17.6,-12.6) W26(18.4,-12.6) Y7(3.2,-13.8) Y8(4,-13.8) Y9(4.8,-13.8) Y10(5.6,-13.8) Y23(16,-13.8) Y24(16.8,-13.8) Y25(17.6,-13.8) Y26(18.4,-13.8)
  round 0.305 smd: A5(1.6,0) A7(3.2,0) A9(4.8,0) A11(6.4,0) A13(8,0) A15(9.6,0) A17(11.2,0) A19(12.8,0) A21(14.4,0) A23(16,0) A25(17.6,0) A27(19.2,0) A28(20,0) AA1(0,-14.4) AA3(0.8,-14.4) AA5(1.6,-14.4) AA6(2.4,-14.4) AA27(19.2,-14.4) AA29(20.4,-14.4) AA31(21.2,-14.4) AB2(0.4,-15.2) AB4(1.2,-15.2) AB6(2.4,-15.2) AB27(19.2,-15.2) AB28(20,-15.2) AB30(20.8,-15.2) AB32(21.6,-15.2) AC1(0,-16) AC3(0.8,-16) AC5(1.6,-16) AC6(2.4,-16) AC7(3.2,-16) AC8(4,-16) AC9(4.8,-16) AC10(5.6,-16) AC23(16,-16) AC24(16.8,-16) AC25(17.6,-16) AC26(18.4,-16) AC27(19.2,-16) AC29(20.4,-16) AC31(21.2,-16) AD2(0.4,-16.8) AD4(1.2,-16.8) AD6(2.4,-16.8) AD7(3.2,-16.8) AD8(4,-16.8) AD9(4.8,-16.8) AD10(5.6,-16.8) AD23(16,-16.8) AD24(16.8,-16.8) AD25(17.6,-16.8) AD26(18.4,-16.8) AD27(19.2,-16.8) AD28(20,-16.8) AD30(20.8,-16.8) AD32(21.6,-16.8) AE1(0,-17.6) AE3(0.8,-17.6) AE5(1.6,-17.6) AE6(2.4,-17.6) AE7(3.2,-17.6) AE8(4,-17.6) AE9(4.8,-17.6) AE10(5.6,-17.6) AE23(16,-17.6) AE24(16.8,-17.6) AE25(17.6,-17.6) AE26(18.4,-17.6) AE27(19.2,-17.6) AE29(20.4,-17.6) AE31(21.2,-17.6) AF2(0.4,-18.4) AF4(1.2,-18.4) AF6(2.4,-18.4) AF7(3.2,-18.4) AF8(4,-18.4) AF9(4.8,-18.4) AF10(5.6,-18.4) AF23(16,-18.4) AF24(16.8,-18.4) AF25(17.6,-18.4) AF26(18.4,-18.4) AF27(19.2,-18.4) AF28(20,-18.4) AF30(20.8,-18.4) AF32(21.6,-18.4) AG1(0,-19.2) AG3(0.8,-19.2) AG5(1.6,-19.2) AG6(2.4,-19.2) AG7(3.2,-19.2) AG8(4,-19.2) AG9(4.8,-19.2) AG10(5.6,-19.2) AG11(6.4,-19.2) AG12(7.2,-19.2) AG13(8,-19.2) AG14(8.8,-19.2) AG15(9.6,-19.2) AG16(10.4,-19.2) AG17(11.2,-19.2) AG18(12,-19.2) AG19(12.8,-19.2) AG20(13.6,-19.2) AG21(14.4,-19.2) AG22(15.2,-19.2) AG23(16,-19.2) AG24(16.8,-19.2) AG25(17.6,-19.2) AG26(18.4,-19.2) AG27(19.2,-19.2) AG29(20.4,-19.2) AG31(21.2,-19.2) AH1(0,-20) AH3(0.8,-20) AH5(1.6,-20) AH6(2.4,-20) AH8(4,-20) AH10(5.6,-20) AH12(7.2,-20) AH14(8.8,-20) AH16(10.4,-20) AH18(12,-20) AH20(13.6,-20) AH22(15.2,-20) AH24(16.8,-20) AH26(18.4,-20) AH28(20,-20) AH30(20.8,-20) AH32(21.6,-20) AJ7(3.2,-20.4) AJ9(4.8,-20.4) AJ11(6.4,-20.4) AJ13(8,-20.4) AJ15(9.6,-20.4) AJ17(11.2,-20.4) AJ19(12.8,-20.4) AJ21(14.4,-20.4) AJ23(16,-20.4) AJ25(17.6,-20.4) AJ27(19.2,-20.4) AK5(1.6,-20.8) AK6(2.4,-20.8) AK8(4,-20.8) AK10(5.6,-20.8) AK12(7.2,-20.8) AK14(8.8,-20.8) AK16(10.4,-20.8) AK18(12,-20.8) AK20(13.6,-20.8) AK22(15.2,-20.8) AK24(16.8,-20.8) AK26(18.4,-20.8) AK28(20,-20.8) AL7(3.2,-21.2) AL9(4.8,-21.2) AL11(6.4,-21.2) AL13(8,-21.2) AL15(9.6,-21.2) AL17(11.2,-21.2) AL19(12.8,-21.2) AL21(14.4,-21.2) AL23(16,-21.2) AL25(17.6,-21.2) AL27(19.2,-21.2) AM5(1.6,-21.6) AM6(2.4,-21.6) AM8(4,-21.6) AM10(5.6,-21.6) AM12(7.2,-21.6) AM14(8.8,-21.6) AM16(10.4,-21.6) AM18(12,-21.6) AM20(13.6,-21.6) AM22(15.2,-21.6) AM24(16.8,-21.6) AM26(18.4,-21.6) AM28(20,-21.6) B6(2.4,-0.4) B8(4,-0.4) B10(5.6,-0.4) B12(7.2,-0.4) B14(8.8,-0.4) B16(10.4,-0.4) B18(12,-0.4) B20(13.6,-0.4) B22(15.2,-0.4) B24(16.8,-0.4) B26(18.4,-0.4) C5(1.6,-0.8) C7(3.2,-0.8) C9(4.8,-0.8) C11(6.4,-0.8) C13(8,-0.8) C15(9.6,-0.8) C17(11.2,-0.8) C19(12.8,-0.8) C21(14.4,-0.8) C23(16,-0.8) C25(17.6,-0.8) C27(19.2,-0.8) C28(20,-0.8) D6(2.4,-1.2) D8(4,-1.2) D10(5.6,-1.2) D12(7.2,-1.2) D14(8.8,-1.2) D16(10.4,-1.2) D18(12,-1.2) D20(13.6,-1.2) D22(15.2,-1.2) D24(16.8,-1.2) D26(18.4,-1.2) E1(0,-1.6) E3(0.8,-1.6) E5(1.6,-1.6) E7(3.2,-1.6) E9(4.8,-1.6) E11(6.4,-1.6) E13(8,-1.6) E15(9.6,-1.6) E17(11.2,-1.6) E19(12.8,-1.6) E21(14.4,-1.6) E23(16,-1.6) E25(17.6,-1.6) E27(19.2,-1.6) E28(20,-1.6) E30(20.8,-1.6) E32(21.6,-1.6) F2(0.4,-2.4) F4(1.2,-2.4) F6(2.4,-2.4) F7(3.2,-2.4) F8(4,-2.4) F9(4.8,-2.4) F10(5.6,-2.4) F11(6.4,-2.4) F12(7.2,-2.4) F13(8,-2.4) F14(8.8,-2.4) F15(9.6,-2.4) F16(10.4,-2.4) F17(11.2,-2.4) F18(12,-2.4) F19(12.8,-2.4) F20(13.6,-2.4) F21(14.4,-2.4) F22(15.2,-2.4) F23(16,-2.4) F24(16.8,-2.4) F25(17.6,-2.4) F26(18.4,-2.4) F27(19.2,-2.4) F28(20,-2.4) F30(20.8,-2.4) F32(21.6,-2.4) G1(0,-3.2) G3(0.8,-3.2) G5(1.6,-3.2) G6(2.4,-3.2) G7(3.2,-3.2) G8(4,-3.2) G9(4.8,-3.2) G10(5.6,-3.2) G23(16,-3.2) G24(16.8,-3.2) G25(17.6,-3.2) G26(18.4,-3.2) G27(19.2,-3.2) G29(20.4,-3.2) G31(21.2,-3.2) H2(0.4,-4) H4(1.2,-4) H6(2.4,-4) H7(3.2,-4) H8(4,-4) H9(4.8,-4) H10(5.6,-4) H23(16,-4) H24(16.8,-4) H25(17.6,-4) H26(18.4,-4) H27(19.2,-4) H28(20,-4) H30(20.8,-4) H32(21.6,-4) J1(0,-4.8) J3(0.8,-4.8) J5(1.6,-4.8) J6(2.4,-4.8) J7(3.2,-4.8) J8(4,-4.8) J9(4.8,-4.8) J10(5.6,-4.8) J23(16,-4.8) J24(16.8,-4.8) J25(17.6,-4.8) J26(18.4,-4.8) J27(19.2,-4.8) J29(20.4,-4.8) J31(21.2,-4.8) K2(0.4,-5.6) K4(1.2,-5.6) K6(2.4,-5.6) K7(3.2,-5.6) K8(4,-5.6) K9(4.8,-5.6) K10(5.6,-5.6) K23(16,-5.6) K24(16.8,-5.6) K25(17.6,-5.6) K26(18.4,-5.6) K27(19.2,-5.6) K28(20,-5.6) K30(20.8,-5.6) K32(21.6,-5.6) L1(0,-6.4) L3(0.8,-6.4) L5(1.6,-6.4) L6(2.4,-6.4) L27(19.2,-6.4) L29(20.4,-6.4) L31(21.2,-6.4) M2(0.4,-7.2) M4(1.2,-7.2) M6(2.4,-7.2) M27(19.2,-7.2) M28(20,-7.2) M30(20.8,-7.2) M32(21.6,-7.2) N1(0,-8) N3(0.8,-8) N5(1.6,-8) N6(2.4,-8) N27(19.2,-8) N29(20.4,-8) N31(21.2,-8) P2(0.4,-8.8) P4(1.2,-8.8) P6(2.4,-8.8) P27(19.2,-8.8) P28(20,-8.8) P30(20.8,-8.8) P32(21.6,-8.8) R1(0,-9.6) R3(0.8,-9.6) R5(1.6,-9.6) R6(2.4,-9.6) R27(19.2,-9.6) R29(20.4,-9.6) R31(21.2,-9.6) T2(0.4,-10.4) T4(1.2,-10.4) T6(2.4,-10.4) T27(19.2,-10.4) T28(20,-10.4) T30(20.8,-10.4) T32(21.6,-10.4) U1(0,-11.2) U3(0.8,-11.2) U5(1.6,-11.2) U6(2.4,-11.2) U27(19.2,-11.2) U29(20.4,-11.2) U31(21.2,-11.2) V2(0.4,-12) V4(1.2,-12) V6(2.4,-12) V27(19.2,-12) V28(20,-12) V30(20.8,-12) V32(21.6,-12) W1(0,-12.8) W3(0.8,-12.8) W5(1.6,-12.8) W6(2.4,-12.8) W27(19.2,-12.8) W29(20.4,-12.8) W31(21.2,-12.8) Y2(0.4,-13.6) Y4(1.2,-13.6) Y6(2.4,-13.6) Y27(19.2,-13.6) Y28(20,-13.6) Y30(20.8,-13.6) Y32(21.6,-13.6)
  round 0.508 smd: AA11(6.4,-14.2) AA12(7.4,-14.2) AA13(8.4,-14.2) AA15(9.4,-14.2) AA16(10.4,-14.2) AA17(11.2,-14.2) AA18(12.2,-14.2) AA20(13.2,-14.2) AA21(14.2,-14.2) AA22(15.2,-14.2) AB11(6.4,-15.2) AB12(7.4,-15.2) AB13(8.4,-15.2) AB15(9.4,-15.2) AB16(10.4,-15.2) AB17(11.2,-15.2) AB18(12.2,-15.2) AB20(13.2,-15.2) AB21(14.2,-15.2) AB22(15.2,-15.2) L11(6.4,-6.4) L12(7.4,-6.4) L13(8.4,-6.4) L15(9.4,-6.4) L16(10.4,-6.4) L17(11.2,-6.4) L18(12.2,-6.4) L20(13.2,-6.4) L21(14.2,-6.4) L22(15.2,-6.4) M11(6.4,-7.4) M12(7.4,-7.4) M13(8.4,-7.4) M15(9.4,-7.4) M16(10.4,-7.4) M17(11.2,-7.4) M18(12.2,-7.4) M20(13.2,-7.4) M21(14.2,-7.4) M22(15.2,-7.4) N11(6.4,-8.4) N12(7.4,-8.4) N13(8.4,-8.4) N15(9.4,-8.4) N16(10.4,-8.4) N17(11.2,-8.4) N18(12.2,-8.4) N20(13.2,-8.4) N21(14.2,-8.4) N22(15.2,-8.4) R11(6.4,-9.4) R12(7.4,-9.4) R13(8.4,-9.4) R15(9.4,-9.4) R16(10.4,-9.4) R17(11.2,-9.4) R18(12.2,-9.4) R20(13.2,-9.4) R21(14.2,-9.4) R22(15.2,-9.4) T11(6.4,-10.4) T12(7.4,-10.4) T13(8.4,-10.4) T15(9.4,-10.4) T16(10.4,-10.4) T17(11.2,-10.4) T18(12.2,-10.4) T20(13.2,-10.4) T21(14.2,-10.4) T22(15.2,-10.4) U11(6.4,-11.2) U12(7.4,-11.2) U13(8.4,-11.2) U15(9.4,-11.2) U16(10.4,-11.2) U17(11.2,-11.2) U18(12.2,-11.2) U20(13.2,-11.2) U21(14.2,-11.2) U22(15.2,-11.2) V11(6.4,-12.2) V12(7.4,-12.2) V13(8.4,-12.2) V15(9.4,-12.2) V16(10.4,-12.2) V17(11.2,-12.2) V18(12.2,-12.2) V20(13.2,-12.2) V21(14.2,-12.2) V22(15.2,-12.2) Y11(6.4,-13.2) Y12(7.4,-13.2) Y13(8.4,-13.2) Y15(9.4,-13.2) Y16(10.4,-13.2) Y17(11.2,-13.2) Y18(12.2,-13.2) Y20(13.2,-13.2) Y21(14.2,-13.2) Y22(15.2,-13.2)
21807-A11-HUDSON-M3_FCBGA_656P
  round 0.381 smd: A3(0.9,0) A31(22.2,0) A33(23.1,0) AL1(0,-22.2) AL3(0.9,-22.2) AL31(22.2,-22.2) AL33(23.1,-22.2) AN1(0,-23.1) AN3(0.9,-23.1) AN31(22.2,-23.1) AN33(23.1,-23.1) C1(0,-0.9) C3(0.9,-0.9) C31(22.2,-0.9) C33(23.1,-0.9)
  round 0.343 smd: A5(1.8,0) A6(2.7,0) A8(4.35,0) A10(5.95,0) A12(7.55,0) A14(9.15,0) A16(10.75,0) A18(12.35,0) A20(13.95,0) A22(15.55,0) A24(17.15,0) A26(18.75,0) A28(20.4,0) A29(21.3,0) AA2(0.4,-14.75) AA4(1.2,-14.75) AA6(2.4,-14.75) AA7(3.35,-14.7) AA8(4.15,-14.7) AA9(4.95,-14.7) AA10(5.75,-14.7) AA11(6.55,-14.7) AA12(7.55,-14.55) AA13(8.55,-14.55) AA14(9.55,-14.55) AA16(10.55,-14.55) AA17(11.55,-14.55) AA18(12.55,-14.55) AA20(13.55,-14.55) AA21(14.55,-14.55) AA22(15.55,-14.55) AA23(16.55,-14.7) AA24(17.35,-14.7) AA25(18.15,-14.7) AA26(18.95,-14.7) AA27(19.75,-14.7) AA28(20.7,-14.75) AA30(21.9,-14.75) AA32(22.7,-14.75) AB1(0,-15.55) AB3(0.8,-15.55) AB5(1.6,-15.55) AB6(2.4,-15.55) AB7(3.35,-15.95) AB8(4.15,-15.95) AB9(4.95,-15.95) AB10(5.75,-15.95) AB11(6.55,-15.95) AB12(7.55,-15.55) AB13(8.55,-15.55) AB14(9.55,-15.55) AB16(10.55,-15.55) AB17(11.55,-15.55) AB18(12.55,-15.55) AB20(13.55,-15.55) AB21(14.55,-15.55) AB22(15.55,-15.55) AB23(16.55,-15.95) AB24(17.35,-15.95) AB25(18.15,-15.95) AB26(18.95,-15.95) AB27(19.75,-15.95) AB28(20.7,-15.55) AB29(21.5,-15.55) AB31(22.3,-15.55) AB33(23.1,-15.55) AC2(0.4,-16.35) AC4(1.2,-16.35) AC6(2.4,-16.35) AC12(7.15,-16.55) AC13(8.4,-16.55) AC15(9.65,-16.55) AC16(10.9,-16.55) AC18(12.2,-16.55) AC19(13.45,-16.55) AC21(14.7,-16.55) AC22(15.95,-16.55) AC28(20.7,-16.35) AC30(21.9,-16.35) AC32(22.7,-16.35) AD1(0,-17.15) AD3(0.8,-17.15) AD5(1.6,-17.15) AD6(2.4,-17.15) AD7(3.45,-17.25) AD8(4.25,-17.25) AD9(5.05,-17.25) AD10(5.85,-17.25) AD12(7.15,-17.35) AD13(8.4,-17.35) AD15(9.65,-17.35) AD16(10.9,-17.35) AD18(12.2,-17.35) AD19(13.45,-17.35) AD21(14.7,-17.35) AD22(15.95,-17.35) AD24(17.25,-17.25) AD25(18.05,-17.25) AD26(18.85,-17.25) AD27(19.65,-17.25) AD28(20.7,-17.15) AD29(21.5,-17.15) AD31(22.3,-17.15) AD33(23.1,-17.15) AE2(0.4,-17.95) AE4(1.2,-17.95) AE6(2.4,-17.95) AE7(3.45,-18.05) AE8(4.25,-18.05) AE9(5.05,-18.05) AE10(5.85,-18.05) AE12(7.15,-18.15) AE13(8.4,-18.15) AE15(9.65,-18.15) AE16(10.9,-18.15) AE18(12.2,-18.15) AE19(13.45,-18.15) AE21(14.7,-18.15) AE22(15.95,-18.15) AE24(17.25,-18.05) AE25(18.05,-18.05) AE26(18.85,-18.05) AE27(19.65,-18.05) AE28(20.7,-17.95) AE30(21.9,-17.95) AE32(22.7,-17.95) AF1(0,-18.75) AF3(0.8,-18.75) AF5(1.6,-18.75) AF6(2.4,-18.75) AF7(3.45,-18.85) AF8(4.25,-18.85) AF9(5.05,-18.85) AF10(5.85,-18.85) AF12(7.15,-18.95) AF13(8.4,-18.95) AF15(9.65,-18.95) AF16(10.9,-18.95) AF18(12.2,-18.95) AF19(13.45,-18.95) AF21(14.7,-18.95) AF22(15.95,-18.95) AF24(17.25,-18.85) AF25(18.05,-18.85) AF26(18.85,-18.85) AF27(19.65,-18.85) AF28(20.7,-18.75) AF29(21.5,-18.75) AF31(22.3,-18.75) AF33(23.1,-18.75) AG2(0.4,-19.55) AG4(1.2,-19.55) AG6(2.4,-19.55) AG7(3.45,-19.65) AG8(4.25,-19.65) AG9(5.05,-19.65) AG10(5.85,-19.65) AG12(7.15,-19.75) AG13(8.4,-19.75) AG15(9.65,-19.75) AG16(10.9,-19.75) AG18(12.2,-19.75) AG19(13.45,-19.75) AG21(14.7,-19.75) AG22(15.95,-19.75) AG24(17.25,-19.65) AG25(18.05,-19.65) AG26(18.85,-19.65) AG27(19.65,-19.65) AG28(20.7,-19.55) AG30(21.9,-19.55) AG32(22.7,-19.55) AH1(0,-20.4) AH3(0.9,-20.4) AH5(1.8,-20.4) AH7(3.55,-20.7) AH8(4.35,-20.7) AH9(5.15,-20.7) AH10(5.95,-20.7) AH11(6.75,-20.7) AH12(7.55,-20.7) AH13(8.35,-20.7) AH14(9.15,-20.7) AH15(9.95,-20.7) AH16(10.75,-20.7) AH17(11.55,-20.7) AH18(12.35,-20.7) AH19(13.15,-20.7) AH20(13.95,-20.7) AH21(14.75,-20.7) AH22(15.55,-20.7) AH23(16.35,-20.7) AH24(17.15,-20.7) AH25(17.95,-20.7) AH26(18.75,-20.7) AH27(19.55,-20.7) AH29(21.3,-20.4) AH31(22.2,-20.4) AH33(23.1,-20.4) AJ1(0,-21.3) AJ3(0.9,-21.3) AJ5(1.8,-21.3) AJ6(2.7,-21.3) AJ8(4.35,-21.5) AJ10(5.95,-21.5) AJ12(7.55,-21.5) AJ14(9.15,-21.5) AJ16(10.75,-21.5) AJ18(12.35,-21.5) AJ20(13.95,-21.5) AJ22(15.55,-21.5) AJ24(17.15,-21.5) AJ26(18.75,-21.5) AJ28(20.4,-21.3) AJ29(21.3,-21.3) AJ31(22.2,-21.3) AJ33(23.1,-21.3) AK7(3.55,-21.9) AK9(5.15,-21.9) AK11(6.75,-21.9) AK13(8.35,-21.9) AK15(9.95,-21.9) AK17(11.55,-21.9) AK19(13.15,-21.9) AK21(14.75,-21.9) AK23(16.35,-21.9) AK25(17.95,-21.9) AK27(19.55,-21.9) AL5(1.8,-22.2) AL6(2.7,-22.2) AL8(4.35,-22.3) AL10(5.95,-22.3) AL12(7.55,-22.3) AL14(9.15,-22.3) AL16(10.75,-22.3) AL18(12.35,-22.3) AL20(13.95,-22.3) AL22(15.55,-22.3) AL24(17.15,-22.3) AL26(18.75,-22.3) AL28(20.4,-22.2) AL29(21.3,-22.2) AM7(3.55,-22.7) AM9(5.15,-22.7) AM11(6.75,-22.7) AM13(8.35,-22.7) AM15(9.95,-22.7) AM17(11.55,-22.7) AM19(13.15,-22.7) AM21(14.75,-22.7) AM23(16.35,-22.7) AM25(17.95,-22.7) AM27(19.55,-22.7) AN5(1.8,-23.1) AN6(2.7,-23.1) AN8(4.35,-23.1) AN10(5.95,-23.1) AN12(7.55,-23.1) AN14(9.15,-23.1) AN16(10.75,-23.1) AN18(12.35,-23.1) AN20(13.95,-23.1) AN22(15.55,-23.1) AN24(17.15,-23.1) AN26(18.75,-23.1) AN28(20.4,-23.1) AN29(21.3,-23.1) B7(3.55,-0.4) B9(5.15,-0.4) B11(6.75,-0.4) B13(8.35,-0.4) B15(9.95,-0.4) B17(11.55,-0.4) B19(13.15,-0.4) B21(14.75,-0.4) B23(16.35,-0.4) B25(17.95,-0.4) B27(19.55,-0.4) C5(1.8,-0.9) C6(2.7,-0.9) C8(4.35,-0.8) C10(5.95,-0.8) C12(7.55,-0.8) C14(9.15,-0.8) C16(10.75,-0.8) C18(12.35,-0.8) C20(13.95,-0.8) C22(15.55,-0.8) C24(17.15,-0.8) C26(18.75,-0.8) C28(20.4,-0.9) C29(21.3,-0.9) D7(3.55,-1.2) D9(5.15,-1.2) D11(6.75,-1.2) D13(8.35,-1.2) D15(9.95,-1.2) D17(11.55,-1.2) D19(13.15,-1.2) D21(14.75,-1.2) D23(16.35,-1.2) D25(17.95,-1.2) D27(19.55,-1.2) E1(0,-1.8) E3(0.9,-1.8) E5(1.8,-1.8) E6(2.7,-1.8) E8(4.35,-1.6) E10(5.95,-1.6) E12(7.55,-1.6) E14(9.15,-1.6) E16(10.75,-1.6) E18(12.35,-1.6) E20(13.95,-1.6) E22(15.55,-1.6) E24(17.15,-1.6) E26(18.75,-1.6) E28(20.4,-1.8) E29(21.3,-1.8) E31(22.2,-1.8) E33(23.1,-1.8) F1(0,-2.7) F3(0.9,-2.7) F5(1.8,-2.7) F7(3.55,-2.4) F8(4.35,-2.4) F9(5.15,-2.4) F10(5.95,-2.4) F11(6.75,-2.4) F12(7.55,-2.4) F13(8.35,-2.4) F14(9.15,-2.4) F15(9.95,-2.4) F16(10.75,-2.4) F17(11.55,-2.4) F18(12.35,-2.4) F19(13.15,-2.4) F20(13.95,-2.4) F21(14.75,-2.4) F22(15.55,-2.4) F23(16.35,-2.4) F24(17.15,-2.4) F25(17.95,-2.4) F26(18.75,-2.4) F27(19.55,-2.4) F29(21.3,-2.7) F31(22.2,-2.7) F33(23.1,-2.7) G2(0.4,-3.55) G4(1.2,-3.55) G6(2.4,-3.55) G7(3.45,-3.45) G8(4.25,-3.45) G9(5.05,-3.45) G10(5.85,-3.45) G12(7.15,-3.35) G13(8.4,-3.35) G15(9.65,-3.35) G16(10.9,-3.35) G18(12.2,-3.35) G19(13.45,-3.35) G21(14.7,-3.35) G22(15.95,-3.35) G24(17.25,-3.45) G25(18.05,-3.45) G26(18.85,-3.45) G27(19.65,-3.45) G28(20.7,-3.55) G30(21.9,-3.55) G32(22.7,-3.55) H1(0,-4.35) H3(0.8,-4.35) H5(1.6,-4.35) H6(2.4,-4.35) H7(3.45,-4.25) H8(4.25,-4.25) H9(5.05,-4.25) H10(5.85,-4.25) H12(7.15,-4.15) H13(8.4,-4.15) H15(9.65,-4.15) H16(10.9,-4.15) H18(12.2,-4.15) H19(13.45,-4.15) H21(14.7,-4.15) H22(15.95,-4.15) H24(17.25,-4.25) H25(18.05,-4.25) H26(18.85,-4.25) H27(19.65,-4.25) H28(20.7,-4.35) H29(21.5,-4.35) H31(22.3,-4.35) H33(23.1,-4.35) J2(0.4,-5.15) J4(1.2,-5.15) J6(2.4,-5.15) J7(3.45,-5.05) J8(4.25,-5.05) J9(5.05,-5.05) J10(5.85,-5.05) J12(7.15,-4.95) J13(8.4,-4.95) J15(9.65,-4.95) J16(10.9,-4.95) J18(12.2,-4.95) J19(13.45,-4.95) J21(14.7,-4.95) J22(15.95,-4.95) J24(17.25,-5.05) J25(18.05,-5.05) J26(18.85,-5.05) J27(19.65,-5.05) J28(20.7,-5.15) J30(21.9,-5.15) J32(22.7,-5.15) K1(0,-5.95) K3(0.8,-5.95) K5(1.6,-5.95) K6(2.4,-5.95) K7(3.45,-5.85) K8(4.25,-5.85) K9(5.05,-5.85) K10(5.85,-5.85) K12(7.15,-5.75) K13(8.4,-5.75) K15(9.65,-5.75) K16(10.9,-5.75) K18(12.2,-5.75) K19(13.45,-5.75) K21(14.7,-5.75) K22(15.95,-5.75) K24(17.25,-5.85) K25(18.05,-5.85) K26(18.85,-5.85) K27(19.65,-5.85) K28(20.7,-5.95) K29(21.5,-5.95) K31(22.3,-5.95) K33(23.1,-5.95) L2(0.4,-6.75) L4(1.2,-6.75) L6(2.4,-6.75) L12(7.15,-6.55) L13(8.4,-6.55) L15(9.65,-6.55) L16(10.9,-6.55) L18(12.2,-6.55) L19(13.45,-6.55) L21(14.7,-6.55) L22(15.95,-6.55) L28(20.7,-6.75) L30(21.9,-6.75) L32(22.7,-6.75) M1(0,-7.55) M3(0.8,-7.55) M5(1.6,-7.55) M6(2.4,-7.55) M7(3.45,-7.15) M8(4.15,-7.15) M9(4.95,-7.15) M10(5.75,-7.15) M11(6.55,-7.15) M12(7.55,-7.55) M13(8.55,-7.55) M14(9.55,-7.55) M16(10.55,-7.55) M17(11.55,-7.55) M18(12.55,-7.55) M20(13.55,-7.55) M21(14.55,-7.55) M22(15.55,-7.55) M23(16.55,-7.15) M24(17.35,-7.15) M25(18.15,-7.15) M26(18.95,-7.15) M27(19.75,-7.15) M28(20.7,-7.55) M29(21.5,-7.55) M31(22.3,-7.55) M33(23.1,-7.55) N2(0.4,-8.35) N4(1.2,-8.35) N6(2.4,-8.35) N7(3.35,-8.4) N8(4.15,-8.4) N9(4.95,-8.4) N10(5.75,-8.4) N11(6.55,-8.4) N12(7.55,-8.55) N13(8.55,-8.55) N14(9.55,-8.55) N16(10.55,-8.55) N17(11.55,-8.55) N18(12.55,-8.55) N20(13.55,-8.55) N21(14.55,-8.55) N22(15.55,-8.55) N23(16.55,-8.4) N24(17.35,-8.4) N25(18.15,-8.4) N26(18.95,-8.4) N27(19.75,-8.4) N28(20.7,-8.35) N30(21.9,-8.35) N32(22.7,-8.35) P1(0,-9.15) P3(0.8,-9.15) P5(1.6,-9.15) P6(2.4,-9.15) P12(7.55,-9.55) P13(8.55,-9.55) P14(9.55,-9.55) P16(10.55,-9.55) P17(11.55,-9.55) P18(12.55,-9.55) P20(13.55,-9.55) P21(14.55,-9.55) P22(15.55,-9.55) P28(20.7,-9.15) P29(21.5,-9.15) P31(22.3,-9.15) P33(23.1,-9.15) R2(0.4,-9.95) R4(1.2,-9.95) R6(2.4,-9.95) R7(3.35,-9.65) R8(4.15,-9.65) R9(4.95,-9.65) R10(5.75,-9.65) R11(6.55,-9.65) R23(16.55,-9.65) R24(17.35,-9.65) R25(18.15,-9.65) R26(18.95,-9.65) R27(19.75,-9.65) R28(20.7,-9.95) R30(21.9,-9.95) R32(22.7,-9.95) T1(0,-10.75) T3(0.8,-10.75) T5(1.6,-10.75) T6(2.4,-10.75) T7(3.35,-10.9) T8(4.15,-10.9) T9(4.95,-10.9) T10(5.75,-10.9) T11(6.55,-10.9) T12(7.55,-10.55) T13(8.55,-10.55) T14(9.55,-10.55) T16(10.55,-10.55) T17(11.55,-10.55) T18(12.55,-10.55) T20(13.55,-10.55) T21(14.55,-10.55) T22(15.55,-10.55) T23(16.55,-10.9) T24(17.35,-10.9) T25(18.15,-10.9) T26(18.95,-10.9) T27(19.75,-10.9) T28(20.7,-10.75) T29(21.5,-10.75) T31(22.3,-10.75) T33(23.1,-10.75) U2(0.4,-11.55) U4(1.2,-11.55) U6(2.4,-11.55) U12(7.55,-11.55) U13(8.55,-11.55) U14(9.55,-11.55) U16(10.55,-11.55) U17(11.55,-11.55) U18(12.55,-11.55) U20(13.55,-11.55) U21(14.55,-11.55) U22(15.55,-11.55) U28(20.7,-11.55) U30(21.9,-11.55) U32(22.7,-11.55) V1(0,-12.35) V3(0.8,-12.35) V5(1.6,-12.35) V6(2.4,-12.35) V7(3.35,-12.2) V8(4.15,-12.2) V9(4.95,-12.2) V10(5.75,-12.2) V11(6.55,-12.2) V12(7.55,-12.55) V13(8.55,-12.55) V14(9.55,-12.55) V16(10.55,-12.55) V17(11.55,-12.55) V18(12.55,-12.55) V20(13.55,-12.55) V21(14.55,-12.55) V22(15.55,-12.55) V23(16.55,-12.2) V24(17.35,-12.2) V25(18.15,-12.2) V26(18.95,-12.2) V27(19.75,-12.2) V28(20.7,-12.35) V29(21.5,-12.35) V31(22.3,-12.35) V33(23.1,-12.35) W2(0.4,-13.15) W4(1.2,-13.15) W6(2.4,-13.15) W7(3.35,-13.45) W8(4.15,-13.45) W9(4.95,-13.45) W10(5.75,-13.45) W11(6.55,-13.45) W23(16.55,-13.45) W24(17.35,-13.45) W25(18.15,-13.45) W26(18.95,-13.45) W27(19.75,-13.45) W28(20.7,-13.15) W30(21.9,-13.15) W32(22.7,-13.15) Y1(0,-13.95) Y3(0.8,-13.95) Y5(1.6,-13.95) Y6(2.4,-13.95) Y12(7.55,-13.55) Y13(8.55,-13.55) Y14(9.55,-13.55) Y16(10.55,-13.55) Y17(11.55,-13.55) Y18(12.55,-13.55) Y20(13.55,-13.55) Y21(14.55,-13.55) Y22(15.55,-13.55) Y28(20.7,-13.95) Y29(21.5,-13.95) Y31(22.3,-13.95) Y33(23.1,-13.95)
ACES_50271-0020N-001_2P
  oval 0.787x1.6 smd: 1(0,0) 2(1.25,0)
  rect 2.108x2.997 smd: 3(3.8,-2.9) 4(-2.55,-2.9)
ACES_50278-00401-001_4P
  oval 0.787x1.905 smd: 1(0,0) 2(1.25,0) 3(2.5,0) 4(3.75,0)
  rect 1.295x3.353 smd: 5(-2.85,-4.925) 6(6.6,-4.925)
ACES_50299-00501-003_5P
  round 1.803 hole 1.803 unplated: (-0.2,5.2) (8.2,5.2)
  oval 0.889x2.388 smd: 1(0,0) 2(2,0) 3(4,0) 4(6,0) 5(8,0)
ACES_50524-00401-P01_4P-T
  oval 0.305x1.295 smd: 1(0,0) 2(1,0) 3(2,0) 4(3,0)
  rect 1.803x2.21 smd: 5(-2.65,-5.65) 6(5.65,-5.65)
ACES_51524-0080N-001_8P
  oval 0.61x1.295 smd: 1(0,0) 2(1,0) 3(2,0) 4(3,0) 5(4,0) 6(5,0) 7(6,0) 8(7,0)
  rect 2.489x2.21 smd: 9(10,-3.05) 10(-3,-3.05)
ACES_51524-0160N-001_16P
  oval 0.61x1.295 smd: 1(0,0) 2(1,0) 3(2,0) 4(3,0) 5(4,0) 6(5,0) 7(6,0) 8(7,0) 9(8,0) 10(9,0) 11(10,0) 12(11,0) 13(12,0) 14(13,0) 15(14,0) 16(15,0)
  rect 2.159x2.21 smd: 17(-2.825,-3.05) 18(17.825,-3.05)
ACES_88231-03041_3P
  oval 0.787x1.905 smd: 1(0,0) 2(1.25,0) 3(2.5,0)
  rect 1.295x3.353 smd: 4(-2.85,-4.925) 5(5.35,-4.925)
ADM1032ARMZ_MSOP8
  oval 0.381x1.626 smd: 1(0,0) 2(0.65,0) 3(1.3,0) 4(1.95,0) 5(1.95,4.3) 6(1.3,4.3) 7(0.65,4.3) 8(0,4.3)
ALC3234-CG_MQFN48_6X6
  oval 0.203x0.889 smd: 1(0,0) 2(0.4,0) 3(0.8,0) 4(1.2,0) 5(1.6,0) 6(2,0) 7(2.4,0) 8(2.8,0) 9(3.2,0) 10(3.6,0) 11(4,0) 12(4.4,0) 25(4.4,6.1) 26(4,6.1) 27(3.6,6.1) 28(3.2,6.1) 29(2.8,6.1) 30(2.4,6.1) 31(2,6.1) 32(1.6,6.1) 33(1.2,6.1) 34(0.8,6.1) 35(0.4,6.1) 36(0,6.1)
  oval 0.889x0.203 smd: 13(5.25,0.85) 14(5.25,1.25) 15(5.25,1.65) 16(5.25,2.05) 17(5.25,2.45) 18(5.25,2.85) 19(5.25,3.25) 20(5.25,3.65) 21(5.25,4.05) 22(5.25,4.45) 23(5.25,4.85) 24(5.25,5.25) 37(-0.85,5.25) 38(-0.85,4.85) 39(-0.85,4.45) 40(-0.85,4.05) 41(-0.85,3.65) 42(-0.85,3.25) 43(-0.85,2.85) 44(-0.85,2.45) 45(-0.85,2.05) 46(-0.85,1.65) 47(-0.85,1.25) 48(-0.85,0.85)
  rect 4.394x4.394 smd: 49(2.2,3.05)
